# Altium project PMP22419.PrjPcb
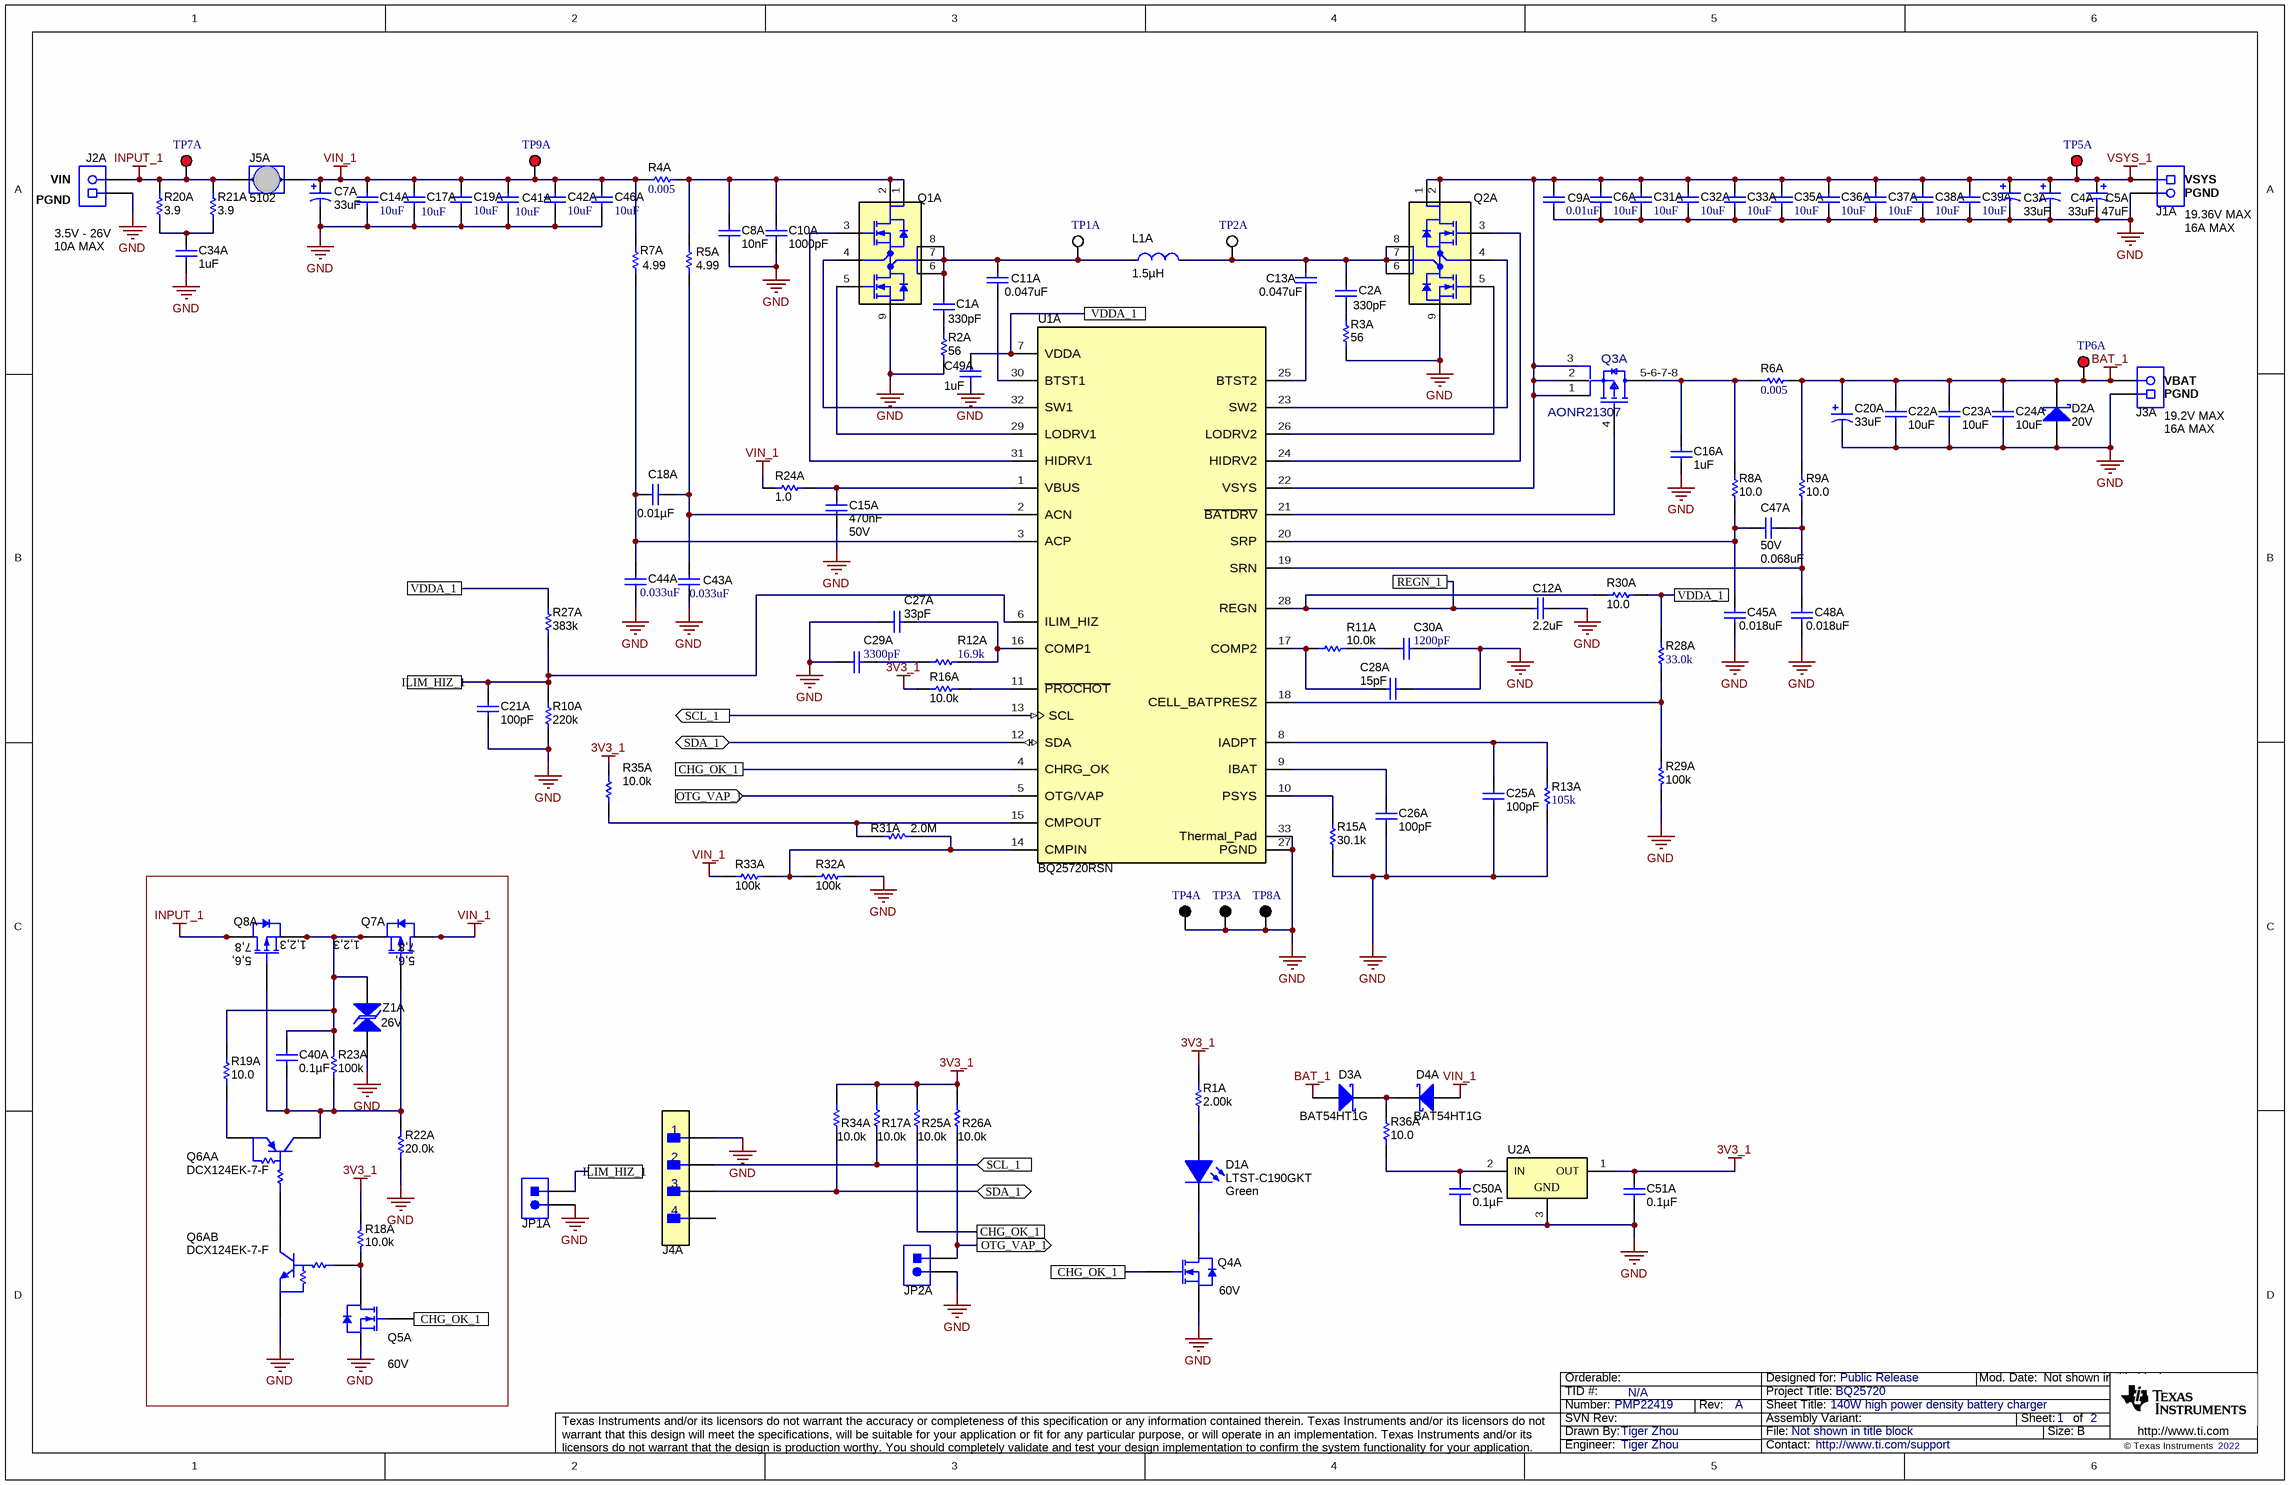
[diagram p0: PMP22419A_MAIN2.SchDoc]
CopyrightYear: 2022; PCB_Layout: Tiger Zhou; PCB_Rev: A; PRJ_Customer: Public Release; PRJ_Engineer: Tiger Zhou; PRJ_Number: PMP22419; PRJ_Title: BQ25720; SCH_Rev: A; TechSupport: http://www.ti.com/support; TID: N/A
1 sheet, 118 parts. Net scope: flat (ports and power ports of the same name join across sheets).
Board file: PMP22419.PcbDoc

## Sheet PMP22419A_MAIN2.SchDoc: 140W high power density battery charger
size 431 x 279 mm; Date: Not shown in title block; ApprovedBy: Not shown in title block; CheckedBy: Not shown in title block; Author: Not shown in title block; CompanyName: Not shown in title block; DrawnBy: Tiger Zhou; Engineer: Not shown in title block; Organization: Not shown in title block; Address1: Not shown in title block; Address2: Not shown in title block; Address3: Not shown in title block; Address4: Not shown in title block; DocumentNumber: 1; Revision: Use project parameter SCH_Rev; SheetNumber: 1; SheetTotal: 2; PageSetup: Record=PageOptions¦CenterHorizontal=True¦CenterVertical=True¦PrintScale=1.00¦XCorrection=1.00¦YCorrection=1.00¦PrintKind=0¦BorderSize=5000000¦LeftOffset=0¦BottomOffset=0¦Orientation=2¦PaperLength=1000¦PaperWidth=1000¦Scale=100¦PaperSource=15¦PrintQuality=600¦MediaType=1¦DitherType=10¦PaperKind=Letter¦PrintScaleMode=1

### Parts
C1A  ValueDisplayed: 330pF  [0603S]  (hidden comment: Capacitor)
C2A  ValueDisplayed: 330pF  [0603S]  (hidden comment: Capacitor)
C3A  ValueDisplayed: 33uF  [7343-31]  (hidden comment: T521D336M035ATE065)
C4A  ValueDisplayed: 33uF  [7343-31]  (hidden comment: T521D336M035ATE065)
C5A  ValueDisplayed: 47uF  [CAPSMT_62_F61]  (hidden comment: Cap_Polarized)
C6A  ValueDisplayed: 10uF  [0805_HV1]  (hidden comment: Capacitor)
C7A  ValueDisplayed: 33uF  [7343-31]  (hidden comment: T521D336M035ATE065)
C8A  Cap_F: 10nF  [0603S]  (hidden comment: GRM188R71H103KA01D)
C9A  ValueDisplayed: 0.01uF  [0603S]  (hidden comment: GRM188R71H103KA01D)
C10A  ValueDisplayed: 1000pF  [0402S]  (hidden comment: C1005NP01H102J050BA)
C11A  ValueDisplayed: 0.047uF  [0603S]  (hidden comment: Capacitor)
C12A  ValueDisplayed: 2.2uF  [0603S]  (hidden comment: Capacitor)
C13A  ValueDisplayed: 0.047uF  [0603S]  (hidden comment: Capacitor)
C14A  ValueDisplayed: 10uF  [0805_HV1]  (hidden comment: Capacitor)
C15A  Cap_F: 470nF  VDC_V: 50V  [0603S]  (hidden comment: C1608X7R1H474K080AC)
C16A  ValueDisplayed: 1uF  [0603S]  (hidden comment: Capacitor)
C17A  ValueDisplayed: 10uF  [0805_HV1]  (hidden comment: Capacitor)
C18A  ValueDisplayed: 0.01µF  [0402S]  (hidden comment: 0402B103K500CT)
C19A  ValueDisplayed: 10uF  [0805_HV1]  (hidden comment: Capacitor)
C20A  ValueDisplayed: 33uF  [7343-31]  (hidden comment: T521D336M035ATE065)
C21A  ValueDisplayed: 100pF  [0402S]  (hidden comment: 04025A101FAT2A)
C22A  ValueDisplayed: 10uF  [1206_180]  (hidden comment: Capacitor)
C23A  ValueDisplayed: 10uF  [1206_180]  (hidden comment: Capacitor)
C24A  ValueDisplayed: 10uF  [1206_180]  (hidden comment: Capacitor)
C25A  ValueDisplayed: 100pF  [0402S]  (hidden comment: 04025A101FAT2A)
C26A  ValueDisplayed: 100pF  [0402S]  (hidden comment: 04025A101FAT2A)
C27A  ValueDisplayed: 33pF  [0402S]  (hidden comment: Capacitor)
C28A  ValueDisplayed: 15pF  [0402S]  (hidden comment: Capacitor)
C29A  ValueDisplayed: 3300pF  [0402S]  (hidden comment: GRM155R71H332KA01D)
C30A  ValueDisplayed: 1200pF  [0402S]  (hidden comment: C0402C122J5GACTU)
C31A  ValueDisplayed: 10uF  [0805_HV1]  (hidden comment: Capacitor)
C32A  ValueDisplayed: 10uF  [0805_HV1]  (hidden comment: Capacitor)
C33A  ValueDisplayed: 10uF  [0805_HV1]  (hidden comment: Capacitor)
C34A  ValueDisplayed: 1uF  [0603S]  (hidden comment: Capacitor)
C35A  ValueDisplayed: 10uF  [0805_HV1]  (hidden comment: Capacitor)
C36A  ValueDisplayed: 10uF  [0805_HV1]  (hidden comment: Capacitor)
C37A  ValueDisplayed: 10uF  [0805_HV1]  (hidden comment: Capacitor)
C38A  ValueDisplayed: 10uF  [0805_HV1]  (hidden comment: Capacitor)
C39A  ValueDisplayed: 10uF  [0805_HV1]  (hidden comment: Capacitor)
C40A  ValueDisplayed: 0.1µF  [0402S]  (hidden comment: 0402BB104KW500)
C41A  ValueDisplayed: 10uF  [0805_HV1]  (hidden comment: Capacitor)
C42A  ValueDisplayed: 10uF  [0805_HV1]  (hidden comment: Capacitor)
C43A  ValueDisplayed: 0.033uF  [0402S]  (hidden comment: CGA2B3X7R1H333K050BB)
C44A  ValueDisplayed: 0.033uF  [0402S]  (hidden comment: CGA2B3X7R1H333K050BB)
C45A  ValueDisplayed: 0.018uF  [0402S]  (hidden comment: GRM155R71H183KA12D)
C46A  ValueDisplayed: 10uF  [0805_HV1]  (hidden comment: Capacitor)
C47A  VDC_V: 50V  ValueDisplayed: 0.068uF  [0402S]  (hidden comment: CGA2B3X7R1H683K050BB)
C48A  ValueDisplayed: 0.018uF  [0402S]  (hidden comment: GRM155R71H183KA12D)
C49A  ValueDisplayed: 1uF  [0603S]  (hidden comment: Capacitor)
C50A  ValueDisplayed: 0.1µF  [0402S]  (hidden comment: 0402BB104KW500)
C51A  ValueDisplayed: 0.1µF  [0402S]  (hidden comment: 0402BB104KW500)
D1A  LTST-C190GKT  value Green  [LED_LTST-C190]
D2A  20V  [SMA]
D3A  BAT54HT1G  [SOD-323]
D4A  BAT54HT1G  [SOD-323]
J1A  Receptacle_2x1  [On-Shore_ED120_2DS]  (value not drawn)
J2A  Receptacle_2x1  [On-Shore_ED120_2DS]  (value not drawn)
J3A  Receptacle_2x1  [On-Shore_ED120_2DS]  (value not drawn)
J4A  22-05-3041  [FP-22-05-3041_HDR4-MFG]  (value not drawn)
J5A  5102  [Keystone_5102]
JP1A  Header_2x1  [CONN_5-146261-1]  (value not drawn)
JP2A  Header_2x1  [CONN_5-146261-1]  (value not drawn)
L1A  Ind_H: 1.5µH  [FP-BMRHDY1010302R2MA1_SMT_IND_11MM2_10MM1-MFG]  (hidden comment: Inductor_Iron)
Q1A  CSD87355Q5D  [DQY0008A]  (value not drawn)
Q2A  CSD87355Q5D  [DQY0008A]  (value not drawn)
Q3A  AONR21307  [FP-AONR21307_DFN8-MFG]
Q4A  value 60V  [SOT-23L]  (hidden comment: MOSFET_N_D3G1S2)
Q5A  value 60V  [SOT-23L]  (hidden comment: MOSFET_N_D3G1S2)
Q6A  DCX124EK-7-F  [SC-74R]  (parts A,B of 2)
Q7A  DMP3035SFG-7  [PowerDI3333-8]  (value not drawn)
Q8A  DMP3035SFG-7  [PowerDI3333-8]  (value not drawn)
R1A  value 2.00k  [0603S]  (hidden comment: Resistor)
R2A  ValueDisplayed: 56  [0603S]  (hidden comment: Resistor)
R3A  ValueDisplayed: 56  [0603S]  (hidden comment: Resistor)
R4A  value 0.005  [1206L]  (hidden comment: WSLP12065L000FEA)
R5A  ValueDisplayed: 4.99  [0402S]  (hidden comment: CRCW04024R99FKED)
R6A  value 0.005  [2010]  (hidden comment: CSNL2010FT5L00)
R7A  ValueDisplayed: 4.99  [0402S]  (hidden comment: CRCW04024R99FKED)
R8A  ValueDisplayed: 10.0  [0402S]  (hidden comment: CRCW040210R0FKED)
R9A  ValueDisplayed: 10.0  [0402S]  (hidden comment: CRCW040210R0FKED)
R10A  ValueDisplayed: 220k  [0402S]  (hidden comment: RC0402FR-07220KL)
R11A  ValueDisplayed: 10.0k  [0402S]  (hidden comment: Resistor)
R12A  ValueDisplayed: 16.9k  [0402S]  (hidden comment: CRCW040216K9FKED)
R13A  ValueDisplayed: 105k  [0402S]  (hidden comment: CRCW0402105KFKED)
R15A  value 30.1k  [0402S]  (hidden comment: CRCW040230K1FKED)
R16A  ValueDisplayed: 10.0k  [0402S]  (hidden comment: CRCW040210K0FKED)
R17A  value 10.0k  [0402S]  (hidden comment: CRCW040210K0FKED)
R18A  ValueDisplayed: 10.0k  [0402S]  (hidden comment: CRCW040210K0FKED)
R19A  ValueDisplayed: 10.0  [1206]  (hidden comment: ERJ-8ENF10R0V)
R20A  value 3.9  [1206]  (hidden comment: Resistor)
R21A  value 3.9  [1206]  (hidden comment: Resistor)
R22A  ValueDisplayed: 20.0k  [0603S]  (hidden comment: CRCW060320K0FKEA)
R23A  ValueDisplayed: 100k  [0402S]  (hidden comment: CRCW0402100KFKED)
R24A  ValueDisplayed: 1.0  [0603S]  (hidden comment: CRCW06031R00JNEA)
R25A  value 10.0k  [0402S]  (hidden comment: CRCW040210K0FKED)
R26A  value 10.0k  [0402S]  (hidden comment: CRCW040210K0FKED)
R27A  ValueDisplayed: 383k  [0402S]  (hidden comment: CRCW0402383KFKED)
R28A  ValueDisplayed: 33.0k  [0402S]  (hidden comment: RC0402FR-0733KL)
R29A  ValueDisplayed: 100k  [0402S]  (hidden comment: CRCW0402100KFKED)
R30A  ValueDisplayed: 10.0  [0402S]  (hidden comment: CRCW040210R0FKED)
R31A  ValueDisplayed: 2.0M  [0402S]  (hidden comment: CRCW04022M00JNED)
R32A  ValueDisplayed: 100k  [0402S]  (hidden comment: CRCW0402100KFKED)
R33A  ValueDisplayed: 100k  [0402S]  (hidden comment: CRCW0402100KFKED)
R34A  value 10.0k  [0402S]  (hidden comment: CRCW040210K0FKED)
R35A  value 10.0k  [0402S]  (hidden comment: CRCW040210K0FKED)
R36A  ValueDisplayed: 10.0  [1206]  (hidden comment: ERJ-8ENF10R0V)
TP1A  5012  [Keystone5012]  (value not drawn)
TP2A  5012  [Keystone5012]  (value not drawn)
TP3A  5011  [Keystone5011]  (value not drawn)
TP4A  5011  [Keystone5011]  (value not drawn)
TP5A  5010  [Keystone5010]  (value not drawn)
TP6A  5010  [Keystone5010]  (value not drawn)
TP7A  5010  [Keystone5010]  (value not drawn)
TP8A  5011  [Keystone5011]  (value not drawn)
TP9A  5010  [Keystone5010]  (value not drawn)
U1A  BQ25720RSN  [RSN0032B-MFG]
U2A  PM-REG-LM3480-SOT3  [DBZ0003A_N]  (value not drawn)
Z1A  value 26V  [SMA_Bi]  (hidden comment: SMAJ26CA)

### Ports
CHG_OK_1, ILIM_HIZ_1, OTG_VAP_1 (in), OTG_VAP_1 (out), REGN_1, SCL_1 (in), SCL_1 (out), SDA_1 (bidir), VDDA_1

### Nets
3V3_1: C51A.2 R1A.2 R16A.1 R17A.2 R18A.2 R25A.2 R26A.1 R34A.2 R35A.1 U2A.1(OUT)
BAT_1: C20A.1(+) C22A.1 C23A.1 C24A.1 D2A.1(K) D3A.2(A) J3A.2 R6A.2 R9A.2 TP6A.1
GND: C3A.2(-) C4A.2(-) C5A.2(-) C6A.2 C7A.2(-) C8A.2 C9A.2 C10A.2 C12A.2 C14A.2 C15A.2 C16A.2 C17A.2 C19A.2 C20A.2(-) C21A.2 C22A.2 C23A.2 C24A.2 C25A.2 C26A.2 C27A.1 C28A.2 C29A.1 C30A.2 C31A.2 C32A.2 C33A.2 C34A.2 C35A.2 C36A.2 C37A.2 C38A.2 C39A.2 C41A.2 C42A.2 C43A.2 C44A.2 C45A.2 C46A.2 C48A.2 C49A.2 C50A.1 C51A.1 D2A.2(A) J1A.2 J2A.1 J3A.1 J4A.1 JP1A.2 JP2A.2 Q1A.9(PGND) Q2A.9(PGND) Q4A.2(S) Q5A.2(S) Q6A.6(E2) R2A.1 R3A.1 R10A.2 R13A.1 R15A.2 R22A.1 R29A.1 R32A.1 TP3A.1 TP4A.1 TP8A.1 U1A.27(PGND) U1A.33(Thermal_Pad) U2A.3(GND) Z1A.2
INPUT_1: J2A.2 J5A.1 Q8A.5(D) Q8A.6(D) Q8A.7(D) Q8A.8(D) Q8A.9(D) R20A.2 R21A.2 TP7A.1
VIN_1: C7A.1(+) C14A.1 C17A.1 C19A.1 C41A.1 C42A.1 C46A.1 D4A.2(A) J5A.2 Q7A.5(D) Q7A.6(D) Q7A.7(D) Q7A.8(D) Q7A.9(D) R4A.1 R7A.2 R24A.1 R33A.2 TP9A.1
VSYS_1: C3A.1(+) C4A.1(+) C5A.1(+) C6A.1 C9A.1 C31A.1 C32A.1 C33A.1 C35A.1 C36A.1 C37A.1 C38A.1 C39A.1 J1A.1 Q2A.1(VIN) Q2A.2(VIN) Q3A.1(S) Q3A.2(S) Q3A.3(S) TP5A.1 U1A.22(VSYS)
CHG_OK_1: Q4A.1(G) Q5A.1(G) R25A.1 U1A.4(CHRG_OK) ; port CHG_OK_1
ILIM_HIZ_1: C21A.1 JP1A.1 R10A.1 R27A.1 U1A.6(ILIM_HIZ) ; port ILIM_HIZ_1
OTG_VAP_1: JP2A.1 R26A.2 U1A.5(OTG/VAP) ; port OTG_VAP_1
REGN_1: C12A.1 R30A.1 U1A.28(REGN) ; port REGN_1
SCL_1: J4A.2 R17A.1 U1A.13(SCL) ; port SCL_1
SDA_1: J4A.3 R34A.1 U1A.12(SDA) ; port SDA_1
VDDA_1: C49A.1 R27A.2 R28A.2 R30A.2 U1A.7(VDDA) ; port VDDA_1
NetC1A_1: C1A.1 C11A.2 L1A.1 Q1A.6(VSW) Q1A.7(VSW) Q1A.8(VSW) TP1A.1
NetC1A_2: C1A.2 R2A.2
NetC2A_1: C2A.1 C13A.2 L1A.2 Q2A.6(VSW) Q2A.7(VSW) Q2A.8(VSW) TP2A.1
NetC2A_2: C2A.2 R3A.2
NetC8A_1: C8A.1 C10A.1 Q1A.1(VIN) Q1A.2(VIN) R4A.2 R5A.2
NetC11A_1: C11A.1 U1A.30(BTST1)
NetC13A_1: C13A.1 U1A.25(BTST2)
NetC15A_1: C15A.1 R24A.2 U1A.1(VBUS)
NetC16A_1: C16A.1 Q3A.5-6-7-8(D) R6A.1 R8A.2
NetC18A_1: C18A.1 C44A.1 R7A.1 U1A.3(ACP)
NetC18A_2: C18A.2 C43A.1 R5A.1 U1A.2(ACN)
NetC25A_1: C25A.1 R13A.2 U1A.8(IADPT)
NetC26A_1: C26A.1 U1A.9(IBAT)
NetC27A_2: C27A.2 R12A.2 U1A.16(COMP1)
NetC28A_1: C28A.1 R11A.1 U1A.17(COMP2)
NetC29A_2: C29A.2 R12A.1
NetC30A_1: C30A.1 R11A.2
NetC34A_1: C34A.1 R20A.1 R21A.1
NetC40A_1: C40A.1 Q6A.4(C1) Q7A.4(G) Q8A.4(G) R22A.2 R23A.1
NetC40A_2: C40A.2 Q7A.1(S) Q7A.2(S) Q7A.3(S) Q8A.1(S) Q8A.2(S) Q8A.3(S) R19A.2 R23A.2 Z1A.1
NetC45A_1: C45A.1 C47A.2 R8A.1 U1A.20(SRP)
NetC47A_1: C47A.1 C48A.1 R9A.1 U1A.19(SRN)
NetC50A_2: C50A.2 R36A.1 U2A.2(IN)
NetD1A_1: D1A.1(A) R1A.1
NetD1A_2: D1A.2(K) Q4A.3(D)
NetD3A_1: D3A.1(K) D4A.1(K) R36A.2
NetQ1A_3: Q1A.3(TG) U1A.31(HIDRV1)
NetQ1A_4: Q1A.4(TGR) U1A.32(SW1)
NetQ1A_5: Q1A.5(BG) U1A.29(LODRV1)
NetQ2A_3: Q2A.3(TG) U1A.24(HIDRV2)
NetQ2A_4: Q2A.4(TGR) U1A.23(SW2)
NetQ2A_5: Q2A.5(BG) U1A.26(LODRV2)
NetQ3A_4: Q3A.4(G) U1A.21(~{BATDRV})
NetQ5A_3: Q5A.3(D) Q6A.5(B2) R18A.1
NetQ6A_1: Q6A.1(C2) Q6A.2(B1)
NetQ6A_3: Q6A.3(E1) R19A.1
NetR15A_1: R15A.1 U1A.10(PSYS)
NetR16A_2: R16A.2 U1A.11(~{PROCHOT})
NetR28A_1: R28A.1 R29A.2 U1A.18(CELL_BATPRESZ)
NetR31A_1: R31A.1 R32A.2 R33A.1 U1A.14(CMPIN)
NetR31A_2: R31A.2 R35A.2 U1A.15(CMPOUT)

Not connected (* = marked no-connect by the designer): J4A 4

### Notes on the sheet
- (near J2A) VIN
- (near J2A) PGND
- 3.5V - 26V
- (near J1A) VSYS
- (near J1A) PGND
- (near J1A) 19.36V MAX
- (near J1A) 16A MAX
- 10A MAX
- (near J3A) PGND
- (near J3A) VBAT
- (near J3A) 19.2V MAX
- (near J3A) 16A MAX

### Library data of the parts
C1A C2A = CMP-0007449-4: CAP, CERM, 330 pF, 50 V, +/- 10%, X7R, 0603; PartNumber: GRM188R71H331KA01D; Manufacturer: MuRata; Polarized: N; Value: 330pF; U/M: EA; Value1: Unknown; VDC_V: 50V; TaMin_C: -55°C; TaMax_C: 125°C; Cap_Case: 0603; SizeAreaWB_mm2: 4.68; SizeZ_mm: 1; SizeX_mm: 1.6; SizeY_mm: 0.8; SizeArea_mm2: 1.28; AEC Category: Q200
C3A C4A C7A C20A = CMP-0011849-2: CAP, TA, 33 uF, 35 V, +/- 20%, 0.065 ohm, SMD; Manufacturer: Kemet; Polarized: Y; CompType: Capacitor; Value: 33uF; U/M: EA; Cap_F: 33µF; VDC_V: 35V; ESR_ohm: 0.065; IRMS_A: 1.9A; TaMin_C: -55°C; TaMax_C: 125°C; AEC Category: Q200; AEC Qualified: N; SizeAreaWB_mm2: 58.59; SizeArea_mm2: 31.39; SizeX_mm: 7.3; SizeY_mm: 4.3; SizeZ_mm: 3.1
C5A = CMP-0012121-3: CAP, Aluminum Polymer, 47 uF, 25 V, +/- 20%, 0.03 ohm, F61 SMD; PartNumber: 25SVPF47M; Manufacturer: Panasonic; Polarized: Y; CompType: Capacitor; Value: 47uF; U/M: EA; Cap_F: 47µF; VDC_V: 25V; ESR_ohm: 0.03; IRMS_A: 2.8A; TaMin_C: -55°C; TaMax_C: 105°C; AEC Category: Q200; SizeAreaWB_mm2: 73.96; SizeZ_mm: 5.8; SizeX_mm: 6.6; SizeArea_mm2: 43.56
C6A C14A C17A C19A C31A C32A C33A C35A C36A C37A C38A C39A C41A C42A C46A = CMP-0007842-2: CAP, CERM, 10 uF, 35 V, +/- 10%, X5R, 0805; PartNumber: C2012X5R1V106K085AC; Manufacturer: TDK; Polarized: N; Value: 10uF; U/M: EA; Cap_F: 10µF; ESR_ohm: 2.818m; Value1: 0.002818 ohm; VDC_V: 35V; IRMS_A: 3.8868A; TaMin_C: -55°C; TaMax_C: 85°C; Cap_Case: 0805; SizeArea_mm2: 2.5; SizeAreaWB_mm2: 6.75; SizeX_mm: 2; SizeY_mm: 1.25; SizeZ_mm: 1.45; AEC Category: Q200
C8A = CMP-0007433-4: CAP, CERM, 0.01 uF, 50 V, +/- 10%, X7R, 0603; Manufacturer: MuRata; Polarized: N; Value: 0.01uF; U/M: EA; Value1: Unknown; VDC_V: 50V; TaMin_C: -55°C; TaMax_C: 125°C; Cap_Case: 0603; AEC Category: Q200; SizeAreaWB_mm2: 4.68; SizeZ_mm: 1; SizeX_mm: 1.6; SizeY_mm: 0.8; SizeArea_mm2: 1.28
C9A = CMP-0007433-4: CAP, CERM, 0.01 uF, 50 V, +/- 10%, X7R, 0603; Manufacturer: MuRata; Polarized: N; Value: 0.01uF; U/M: EA; Cap_F: 10nF; Value1: Unknown; VDC_V: 50V; TaMin_C: -55°C; TaMax_C: 125°C; Cap_Case: 0603; SizeAreaWB_mm2: 4.68; SizeZ_mm: 1; SizeX_mm: 1.6; SizeY_mm: 0.8; SizeArea_mm2: 1.28; AEC Category: Q200
C10A = CMP-0006254-2: CAP, CERM, 1000 pF, 50 V, +/- 5%, C0G/NP0, 0402; Manufacturer: TDK; Polarized: N; Value: 1000pF; U/M: EA; Cap_F: 1nF; Value1: Unknown; VDC_V: 50V; TaMin_C: -55°C; TaMax_C: 150°C; Cap_Case: 0402; SizeAreaWB_mm2: 3; SizeZ_mm: 0.6; SizeX_mm: 1; SizeY_mm: 0.5; AEC Category: Q200
C11A C13A = CMP-0007423-4: CAP, CERM, 0.047 uF, 25 V, +/- 10%, X7R, 0603; PartNumber: GRM188R71E473KA01D; Manufacturer: MuRata; Polarized: N; U/M: EA; Cap_F: 47nF; Value1: Unknown; VDC_V: 25V; TaMin_C: -55°C; TaMax_C: 125°C; Cap_Case: 0603; SizeAreaWB_mm2: 4.68; SizeZ_mm: 1; SizeX_mm: 1.6; SizeY_mm: 0.8; SizeArea_mm2: 1.28; AEC Category: Q200
C12A = CMP-0007356-5: CAP, CERM, 2.2 uF, 35 V, +/- 10%, X5R, 0603; PartNumber: GRM188R6YA225KA12D; Manufacturer: MuRata; Polarized: N; Value: 2.2uF; U/M: EA; Cap_F: 2.2µF; Value1: Unknown; VDC_V: 35V; TaMin_C: -55°C; TaMax_C: 85°C; Cap_Case: 0603; SizeAreaWB_mm2: 4.68; SizeZ_mm: 1; SizeX_mm: 1.6; SizeY_mm: 0.8; SizeArea_mm2: 1.28; AEC Category: Q200
C15A = CMP-0007050-4: CAP, CERM, 0.47 uF, 50 V, +/- 10%, X7R, 0603; Manufacturer: TDK; Polarized: N; Value: 0.47uF; U/M: EA; ESR_ohm: 10.974m; Value1: 0.010974 ohm; IRMS_A: 1.5748A; TaMin_C: -55°C; TaMax_C: 125°C; Cap_Case: 0603; AEC Category: Q200; SizeAreaWB_mm2: 4.68; SizeZ_mm: 1; SizeX_mm: 1.6; SizeY_mm: 0.8; SizeArea_mm2: 1.28
C16A C34A C49A = CMP-0007405-4: CAP, CERM, 1 uF, 25 V, +/- 10%, X7R, 0603; PartNumber: GRM188R71E105KA12D; Manufacturer: MuRata; Polarized: N; Value: 1uF; U/M: EA; Cap_F: 1µF; Value1: Unknown; VDC_V: 25V; TaMin_C: -55°C; TaMax_C: 125°C; Cap_Case: 0603; SizeAreaWB_mm2: 4.68; SizeZ_mm: 1; SizeX_mm: 1.6; SizeY_mm: 0.8; SizeArea_mm2: 1.28; AEC Category: Q200
C18A = CMP-0085842-1: CAP, CERM, 0.01 µF, 50 V,+/- 10%, X7R, 0402; Manufacturer: Walsin; Polarized: N; Value: 0.01uF; U/M: EA; Cap_F: 10nF; VDC_V: 50V; TaMin_C: -55°C; TaMax_C: 125°C; Cap_Case: 0402; AEC Category: Q200; SizeAreaWB_mm2: 3; SizeZ_mm: 0.6; SizeX_mm: 1; SizeY_mm: 0.5
C21A C25A C26A = CMP-0006196-2: CAP, CERM, 100 pF, 50 V, +/- 1%, C0G/NP0, 0402; Manufacturer: AVX; Value: 100pF; VDC_V: 50V; SizeZ_mm: 0.6; AEC Qualified: N; TaMin_C: -55°C; SizeAreaWB_mm2: 3; Value1: Unknown; U/M: EA; TaMax_C: 125°C; SizeX_mm: 1; SizeY_mm: 0.5; Cap_Case: 0402; AEC Category: Q200
C22A C23A C24A = CMP-0008965-2: CAP, CERM, 10 uF, 25 V, +/- 10%, X7R, 1206; PartNumber: GRM31CR71E106KA12L; Manufacturer: MuRata; Polarized: N; Value: 10uF; U/M: EA; Cap_F: 10µF; Value1: Unknown; VDC_V: 25V; TaMin_C: -55°C; TaMax_C: 125°C; Cap_Case: 2220; SizeArea_mm2: 5.12; SizeAreaWB_mm2: 10.92; SizeX_mm: 3.2; SizeY_mm: 1.6; SizeZ_mm: 1.8; AEC Category: Q200
C27A = CMP-0006454-2: CAP, CERM, 33 pF, 50 V, +/- 5%, C0G/NP0, 0402; PartNumber: GRM1555C1H330JA01D; Manufacturer: MuRata; Polarized: N; Value: 33pF; U/M: EA; Value1: Unknown; VDC_V: 50V; TaMin_C: -55°C; TaMax_C: 125°C; Cap_Case: 0402; AEC Category: Q200; SizeArea_mm2: 0.5; SizeAreaWB_mm2: 3; SizeX_mm: 1; SizeZ_mm: 0.6
C28A = CMP-0006420-2: CAP, CERM, 15 pF, 50 V, +/- 5%, C0G/NP0, 0402; PartNumber: GRM1555C1H150JA01D; Manufacturer: MuRata; Polarized: N; Value: 15pF; U/M: EA; Value1: Unknown; VDC_V: 50V; TaMin_C: -55°C; TaMax_C: 125°C; Cap_Case: 0402; AEC Category: Q200; SizeAreaWB_mm2: 3; SizeZ_mm: 0.6; SizeX_mm: 1; SizeY_mm: 0.5
C29A = CMP-0006688-2: CAP, CERM, 3300 pF, 50 V, +/- 10%, X7R, 0402; Manufacturer: MuRata; Polarized: N; Value: 3300pF; U/M: EA; Cap_F: 3.3nF; Value1: Unknown; VDC_V: 50V; TaMin_C: -55°C; TaMax_C: 125°C; Cap_Case: 0402; AEC Category: Q200; SizeAreaWB_mm2: 3; SizeZ_mm: 0.6; SizeX_mm: 1; SizeY_mm: 0.5
C30A = CMP-0006240-2: CAP, CERM, 1200 pF, 50 V, +/- 5%, C0G/NP0, 0402; Manufacturer: Kemet; Polarized: N; Value: 1200pF; U/M: EA; Cap_F: 1.2nF; Value1: Unknown; VDC_V: 50V; TaMin_C: -55°C; TaMax_C: 125°C; Cap_Case: 0402; AEC Category: Q200; SizeAreaWB_mm2: 3; SizeZ_mm: 0.6; SizeX_mm: 1; SizeY_mm: 0.5
C40A C50A C51A = CMP-0860983-1: CAP, CERM, 0.1 µF, 50 V,+/- 10%, X7R, 0402; Manufacturer: Passive Plus; Polarized: N; Value: 0.1uF; U/M: EA; Cap_F: 100nF; VDC_V: 50V; TaMin_C: -55°C; TaMax_C: 125°C; Cap_Case: 0402; SizeAreaWB_mm2: 3; SizeZ_mm: 0.6; SizeX_mm: 1; SizeY_mm: 0.5; AEC Category: Q200
C43A C44A = CMP-0006329-2: CAP, CERM, 0.033 uF, 50 V, +/- 10%, X7R, AEC-Q200 Grade 1, 0402; Manufacturer: TDK; Polarized: N; U/M: EA; Cap_F: 33nF; ESR_ohm: 98.477m; Value1: 0.098477 ohm; VDC_V: 50V; IRMS_A: 530.78mA; TaMin_C: -55°C; TaMax_C: 125°C; Cap_Case: 0402; AEC Category: Q200; AEC Qualified: Y; AEC Grade: 1; SizeArea_mm2: 0.5; SizeAreaWB_mm2: 3; SizeZ_mm: 0.6
C45A C48A = CMP-0006681-2: CAP, CERM, 0.018 uF, 50 V, +/- 10%, X7R, 0402; Manufacturer: MuRata; Polarized: N; U/M: EA; Cap_F: 18nF; Value1: Unknown; VDC_V: 50V; TaMin_C: -55°C; TaMax_C: 125°C; Cap_Case: 0402; AEC Category: Q200; SizeArea_mm2: 0.5; SizeAreaWB_mm2: 3; SizeX_mm: 1; SizeZ_mm: 0.6
C47A = CMP-0006331-2: CAP, CERM, 0.068 uF, 50 V, +/- 10%, X7R, AEC-Q200 Grade 1, 0402; Manufacturer: TDK; TaMin_C: -55°C; ESR_ohm: 0.05606; Polarized: N; SizeAreaWB_mm2: 3; Value1: 0.05606 ohm; U/M: EA; TaMax_C: 125°C; SizeZ_mm: 0.6; SizeX_mm: 1; SizeY_mm: 0.5; Cap_Case: 0402; AEC Qualified: Y; Cap_F: 68nF; IRMS_A: 684.724mA; AEC Category: Q200
D1A = CMP-0002827-3: LED, Green, SMD; Manufacturer: Lite-On; Vf_V: 2.1V; Io_A: 20mA; Power_TotalModule: 100mW; Value1: 0.1W
D2A = CMP-0028399-2: Diode, Schottky, 20 V, 2 A, SMA; PartNumber: B220A-13-F; Manufacturer: Diodes Inc.; Vf_V: 500mV; Value1: 2A; Value2: 0.5V; TJmax_C: 150°C; RJC_CperW: 20; AEC Category: Q101; Green_Lifecycle: Active; Green_REACh: Passed; SizeArea_mm2: 16.3228; SizeAreaWB_mm2: 37.3428; SizeX_mm: 5.59; SizeY_mm: 2.92; SizeZ_mm: 2.87
D3A D4A = CMP-0028455-2: Diode, Schottky, 30 V, 0.2 A, SOD-323; Manufacturer: ON Semiconductor; Value: 30V; Vf_V: 350mV; Value1: 0.2A; Value2: 0.35V; Io_A: 200mA; Green_Lifecycle: Active; SizeAreaWB_mm2: 8.695; Green_REACh: Passed; SizeZ_mm: 1; SizeX_mm: 2.7; SizeY_mm: 1.35; SizeArea_mm2: 3.645; AEC Category: Q101
J1A J2A J3A = CMP-0074910-1: Terminal Block, 5.08 mm, 2x1, Brass, TH; PartNumber: ED120/2DS; Manufacturer: On-Shore Technology; U/M: EA; Cert_VDE: Y; CNHeader: False; Current_A: 15A; Green_Lifecycle: Not Set; Shrouded: N; Gender: Female; Green_REACh: Incomplete; Voltage_V: 300V; Row_Count: 1; Pitch_mm: 5.08; CT: True
J4A = CMP-0089047-2: Connector Header Through Hole, Right Angle 4 position 0.100" (2.54mm); Manufacturer: Molex; PartNumber: 0022053041; Row_Count: 1; Current_A: 4A; ContactFinish: Tin,Nickel; Voltage_V: 500V
J5A = CMP-0055135-1: Shorting Jumper, 5.375mm, 2 Position, Tin, SMT; Manufacturer: Keystone; CNHeader: FALSE; Pitch_mm: 5.375
JP1A JP2A = CMP-0054947-1: Header, 100mil, 2x1, Gold, TH; PartNumber: 5-146261-1; Manufacturer: TE Connectivity; SymbolCreator: a0412235; U/M: EA; CT: FALSE; Green_REACh: Passed; CNHeader: TRUE; Green_Lifecycle: Active
L1A = CMP-0088941-1: 2.2µH Shielded Wirewound Inductor 13A 9mOhm Max 10x10x3mm; PartNumber: BMRHDY1010302R2MA1; Manufacturer: Chilisin Electronics; SizeZ_mm: 3mm; Material: Magnetic Metal Powder; DCR_ohm: 9m; Tolerance_%: 20%; AEC Qualified: No; Test Frequency: 100kHz; Isat: 16A
Q1A Q2A = CMP-0000606-2: MOSFET, 2-CH, N-CH, 30 V, 45 A, DQY0008A (LSON-CLIP-8); Manufacturer: Texas Instruments; Alternate Manufacturer: None; ChType: N; QgTyp_nC: 10.5; SizeAreaWB_mm2: 56; SizeArea_mm2: 30; IdsMax_A: 45A; VdsMax_V: 30V; Rdson45_ohm: 4.7m; Vgs_V: 10V; AEC Category: Q101; Value: 30V; SizeZ_mm: 1.6; ChMode: Enhancement; SizeY_mm: 5; Value2: 10.5 nC; Value1: 0.004; SizeX_mm: 6
Q3A = CMP-0088961-1: MOSFET P-CH 30V 3X3 DFN; Manufacturer: Alpha & Omega Semiconductor; SizeZ_mm: 0.9mm; IdsMax_A: -24A; Vgs_V: 25V; AEC Qualified: No; Rdson45_ohm: 9.2m; ChMode: False; VdsMax_V: -1V; QgTyp_nC: 35nC @ -10V; Threshold Vgs Max: -2.3V; Reverse Recovery Time: 13.3ns; Power_W: 5W; TJmax_C: +150°C; Drain To Source Breakdown Voltage: -30V; Input Capacitace At Vds: 1995pF @ -15V; Reverse Recovery Charge: 20nC; Threshold Vgs Min: -1.3V; Number Of Channels: 1; Pulse Drain Current: -82A; Turn On Delay Time: 11ns; Rthja Max: 45°C/W; Standoff Height: 0mm; Turn Off Delay Time: 43.5ns; Typ Forward Diode Voltage: -0.7V
Q4A = CMP-0000772-1: MOSFET, N-CH, 60 V, 0.26 A, SOT-23; PartNumber: 2N7002ET1G; Manufacturer: ON Semiconductor; Alternate Manufacturer: None; U/M: EA; ChType: N; Rdson45_ohm: 3; Value2: 0.81 nC; QgTyp_nC: 0.81; Vgs_V: 20V; IdsMax_A: 2.6dA; AEC Category: Q101; SizeZ_mm: 1.1; SizeX_mm: 2.5; SizeArea_mm2: 7.5; SizeAreaWB_mm2: 14
Q5A = CMP-0000772-1: MOSFET, N-CH, 60 V, 0.26 A, SOT-23; PartNumber: 2N7002ET1G; Manufacturer: ON Semiconductor; Alternate Manufacturer: None; U/M: EA; ChType: N; Rdson45_ohm: 3; Value2: 0.81 nC; QgTyp_nC: 0.81; Vgs_V: 20V; IdsMax_A: 2.6dA; SizeZ_mm: 1.1; SizeX_mm: 2.5; SizeArea_mm2: 7.5; AEC Category: Q101; SizeAreaWB_mm2: 14
Q6A = CMP-0000514-2: Transistor, NPN/PNP Pair, 50 V, 0.05 A, SC-74R; Manufacturer: Diodes Inc.; CompType: BJT; U/M: EA; Value1: 0.05 A; Value2: 600; Value: 50 V; SymbolCreator: Altium; PNP: 1; Vceo_V: 50V; Vcesat1_V: 3dV; IcRated_A: 50mA; TaMin_C: -55°C; TaMax_C: 150°C; SizeX_mm: 2.8; SizeY_mm: 3; SizeZ_mm: 1.4; SizeArea_mm2: 8.4; AEC Category: Q101; SizeAreaWB_mm2: 15.2
Q7A Q8A = CMP-0000041-3: MOSFET, P-CH, -30 V, -8.5 A, AEC-Q101, 8-PowerVDFN; Manufacturer: Diodes Inc.; Alternate Manufacturer: None; ChType: P; Value: -30V; Value2: 35.5 nC; QgTyp_nC: 35.5; Vgs_V: -25V; IdsMax_A: -8.5A; SizeZ_mm: 0.8; SizeX_mm: 3.3; AEC Qualified: Y; SizeArea_mm2: 10.89; AEC Category: Q101; SizeAreaWB_mm2: 18.49; ChMode: Enhancement
R1A = CMP-0022268-4: RES, 2.00 k, 1%, 0.1 W, AEC-Q200 Grade 0, 0603; PartNumber: CRCW06032K00FKEA; Manufacturer: Vishay-Dale; Res_ohm: 2k; Value_Code: 2k00; Power_W: 100mW; Value2: 0.1W; VDC_V: 75V; TempCo: 100 ppm/C; EIA_Code: E96; U/M: EA; SizeX_mm: 1.6; SizeY_mm: 0.8; SizeZ_mm: 1; SizeArea_mm2: 1.28; AEC Qualified: Y; AEC Category: Q200; AEC Grade: 0
R2A R3A = CMP-0025829-4: RES, 56, 5%, 0.1 W, AEC-Q200 Grade 0, 0603; PartNumber: CRCW060356R0JNEA; Manufacturer: Vishay-Dale; Value: 56; Value_Code: 56R0; Power_W: 100mW; Value2: 0.1W; VDC_V: 75V; TempCo: 200 ppm/C; EIA_Code: E24; U/M: EA; SizeX_mm: 1.6; SizeY_mm: 0.8; SizeZ_mm: 1; SizeArea_mm2: 1.28; AEC Qualified: Y; AEC Category: Q200; AEC Grade: 0
R4A = CMP-0084411-1: RES, 0.005, 1%, 1 W, AEC-Q200 Grade 0, 1206; Manufacturer: Vishay-Dale; Res_ohm: 5m; Value_Code: 5L000; Power_W: 1W; TempCo: 110 ppm/C; EIA_Code: E96; SizeX_mm: 3.2; SizeY_mm: 1.6; SizeZ_mm: 1.35; SizeArea_mm2: 5.12; AEC Qualified: Y; AEC Category: Q200; AEC Grade: 0; Green_REACh: Passed; Green_Lifecycle: Active; SizeAreaWB_mm2: 10.92
R5A R7A = CMP-0026434-2: RES, 4.99, 1%, 0.063 W, AEC-Q200 Grade 0, 0402; Manufacturer: Vishay-Dale; Value: 4.99; Value_Code: 4R99; Power_W: 63mW; Value2: 0.063W; VDC_V: 50V; TempCo: 100 ppm/C; EIA_Code: E96; AEC Category: Q200; AEC Qualified: Y; AEC Grade: 0; SizeArea_mm2: 0.5; SizeX_mm: 1; SizeZ_mm: 0.6
R6A = CMP-0016512-2: RES, 0.005, 1%, 1.5 W, 2010; Manufacturer: Stackpole Electronics Inc; Res_ohm: 5m; Value_Code: 5L000; Power_W: 1.5W; TempCo: 50 ppm/C; EIA_Code: E96; U/M: EA; SizeX_mm: 5; SizeY_mm: 2.5; SizeZ_mm: 1.66; SizeArea_mm2: 12.5; AEC Category: Q200
R8A R9A R30A = CMP-0025963-3: RES, 10.0, 1%, 0.063 W, AEC-Q200 Grade 0, 0402; Manufacturer: Vishay-Dale; Value: 10.0; Res_ohm: 10; Value_Code: 10R0; Power_W: 63mW; Value2: 0.063W; VDC_V: 50V; TempCo: 100 ppm/C; EIA_Code: E96; SizeX_mm: 1; SizeY_mm: 0.5; SizeZ_mm: 0.6; AEC Qualified: Y; AEC Category: Q200; AEC Grade: 0
R10A = CMP-0026728-1: RES, 220 k, 1%, 0.0625 W, 0402; Manufacturer: Yageo America; Value: 220k; Power_W: 62.5mW; VDC_V: 50V; TempCo: 100 ppm/C; SizeX_mm: 1; SizeY_mm: 0.5; SizeZ_mm: 0.6; AEC Qualified: N; AEC Category: Q200; U/M: EA
R11A = CMP-0025958-3: RES, 10.0 k, 1%, 0.063 W, AEC-Q200 Grade 0, 0402; PartNumber: CRCW040210K0FKED; Manufacturer: Vishay-Dale; Value: 10.0k; Res_ohm: 10k; Value_Code: 10k0; Power_W: 63mW; Value2: 0.063W; VDC_V: 50V; TempCo: 100 ppm/C; EIA_Code: E96; U/M: EA; AEC Category: Q200; AEC Qualified: Y; AEC Grade: 0; SizeArea_mm2: 0.5; SizeX_mm: 1; SizeZ_mm: 0.6
R12A = CMP-0026042-3: RES, 16.9 k, 1%, 0.063 W, AEC-Q200 Grade 0, 0402; Manufacturer: Vishay-Dale; Value: 16.9k; Value_Code: 16k9; Power_W: 63mW; Value2: 0.063W; VDC_V: 50V; TempCo: 100 ppm/C; EIA_Code: E96; AEC Category: Q200; AEC Qualified: Y; AEC Grade: 0; SizeX_mm: 1; SizeY_mm: 0.5; SizeZ_mm: 0.6
R13A = CMP-0025954-3: RES, 105 k, 1%, 0.063 W, AEC-Q200 Grade 0, 0402; Manufacturer: Vishay-Dale; Value: 105k; Power_W: 63mW; Value2: 0.063W; VDC_V: 50V; TempCo: 100 ppm/C; EIA_Code: E96; AEC Category: Q200; AEC Qualified: Y; AEC Grade: 0; SizeArea_mm2: 0.5; SizeX_mm: 1; SizeZ_mm: 0.6
R15A = CMP-0026284-2: RES, 30.1 k, 1%, 0.063 W, AEC-Q200 Grade 0, 0402; Manufacturer: Vishay-Dale; Value_Code: 30k1; Power_W: 63mW; Value2: 0.063W; VDC_V: 50V; TempCo: 100 ppm/C; EIA_Code: E96; SizeX_mm: 1; SizeY_mm: 0.5; SizeZ_mm: 0.6; AEC Qualified: Y; AEC Category: Q200; AEC Grade: 0
R16A R18A = CMP-0025958-3: RES, 10.0 k, 1%, 0.063 W, AEC-Q200 Grade 0, 0402; Manufacturer: Vishay-Dale; Value: 10.0k; Res_ohm: 10k; Value_Code: 10k0; Power_W: 63mW; Value2: 0.063W; VDC_V: 50V; TempCo: 100 ppm/C; EIA_Code: E96; SizeX_mm: 1; SizeY_mm: 0.5; SizeZ_mm: 0.6; AEC Qualified: Y; AEC Category: Q200; AEC Grade: 0
R17A R25A R26A R34A R35A = CMP-0025958-3: RES, 10.0 k, 1%, 0.063 W, AEC-Q200 Grade 0, 0402; Manufacturer: Vishay-Dale; Res_ohm: 10k; Value_Code: 10k0; Power_W: 63mW; Value2: 0.063W; VDC_V: 50V; TempCo: 100 ppm/C; EIA_Code: E96; SizeX_mm: 1; SizeY_mm: 0.5; SizeZ_mm: 0.6; AEC Qualified: Y; AEC Category: Q200; AEC Grade: 0
R19A R36A = CMP-0017299-3: RES, 10.0, 1%, 0.25 W, AEC-Q200 Grade 0, 1206; Manufacturer: Panasonic; Value: 10.0; Res_ohm: 10; Value_Code: 10R0; Power_W: 250mW; Value2: 0.25W; VDC_V: 200V; TempCo: 100 ppm/C; EIA_Code: E96; SizeX_mm: 3.2; SizeY_mm: 1.6; SizeZ_mm: 1.35; SizeArea_mm2: 5.12; AEC Qualified: Y; AEC Category: Q200; AEC Grade: 0; SizeAreaWB_mm2: 10.92
R20A R21A = CMP-0018679-3: RES, 3.9, 5%, 0.25 W, AEC-Q200 Grade 0, 1206; PartNumber: CRCW12063R90JNEA; Manufacturer: Vishay-Dale; Value_Code: 3R90; Power_W: 250mW; Value2: 0.25W; VDC_V: 200V; TempCo: 200 ppm/C; EIA_Code: E24; U/M: EA; SizeX_mm: 3.2; SizeY_mm: 1.6; SizeZ_mm: 1.35; SizeArea_mm2: 5.12; AEC Qualified: Y; AEC Category: Q200; AEC Grade: 0
R22A = CMP-0022204-4: RES, 20.0 k, 1%, 0.1 W, AEC-Q200 Grade 0, 0603; Manufacturer: Vishay-Dale; Value: 20.0k; Res_ohm: 20k; Value_Code: 20k0; Power_W: 100mW; Value2: 0.1W; VDC_V: 75V; TempCo: 100 ppm/C; EIA_Code: E96; SizeX_mm: 1.6; SizeY_mm: 0.8; SizeZ_mm: 1; SizeArea_mm2: 1.28; AEC Qualified: Y; AEC Category: Q200; AEC Grade: 0
R23A R29A = CMP-0025950-3: RES, 100 k, 1%, 0.063 W, AEC-Q200 Grade 0, 0402; Manufacturer: Vishay-Dale; Value: 100k; Power_W: 63mW; Value2: 0.063W; VDC_V: 50V; TempCo: 100 ppm/C; EIA_Code: E96; SizeX_mm: 1; SizeY_mm: 0.5; SizeZ_mm: 0.6; AEC Qualified: Y; AEC Category: Q200; AEC Grade: 0
R24A = CMP-0025743-4: RES, 1.0, 5%, 0.1 W, AEC-Q200 Grade 0, 0603; Manufacturer: Vishay-Dale; Value: 1.0; Res_ohm: 1; Value_Code: 1R00; Power_W: 100mW; Value2: 0.1W; VDC_V: 75V; TempCo: 200 ppm/C; EIA_Code: E24; AEC Category: Q200; AEC Qualified: Y; AEC Grade: 0; SizeX_mm: 1.6; SizeY_mm: 0.8; SizeArea_mm2: 1.28
R27A = CMP-0026321-2: RES, 383 k, 1%, 0.063 W, AEC-Q200 Grade 0, 0402; Manufacturer: Vishay-Dale; Value: 383k; Power_W: 63mW; Value2: 0.063W; VDC_V: 50V; TempCo: 100 ppm/C; EIA_Code: E96; SizeX_mm: 1; SizeY_mm: 0.5; SizeZ_mm: 0.6; AEC Qualified: Y; AEC Category: Q200; AEC Grade: 0
R28A = CMP-0078584-1: RES, 33.0 k, 1%, 0.063 W, 0402; Manufacturer: Yageo America; Power_W: 63mW; TempCo: 100 ppm/C; Value_Code: 33k0; Value: 33.0k; Res_ohm: 33k; SizeX_mm: 1; SizeY_mm: 0.5; SizeZ_mm: 0.6; Value2: 0.063W; AEC Qualified: N; AEC Category: Q200
R31A = CMP-0026893-2: RES, 2.0 M, 5%, 0.063 W, AEC-Q200 Grade 0, 0402; Manufacturer: Vishay-Dale; Value: 2.0Meg; Res_ohm: 2M; Value_Code: 2M00; Power_W: 63mW; Value2: 0.063W; VDC_V: 50V; TempCo: 200 ppm/C; EIA_Code: E24; SizeX_mm: 1; SizeY_mm: 0.5; SizeZ_mm: 0.6; AEC Qualified: Y; AEC Category: Q200; AEC Grade: 0
R32A R33A = CMP-0025950-3: RES, 100 k, 1%, 0.063 W, AEC-Q200 Grade 0, 0402; Manufacturer: Vishay-Dale; Power_W: 63mW; TempCo: 100 ppm/C; Value: 100k; EIA_Code: E96; SizeX_mm: 1; SizeY_mm: 0.5; SizeZ_mm: 0.6; Value2: 0.063W; AEC Qualified: Y; VDC_V: 50V; AEC Category: Q200; AEC Grade: 0
TP1A TP2A = CMP-0055149-1: Test Point, Multipurpose, White, TH; Manufacturer: Keystone; CNHeader: FALSE; Green_Lifecycle: Active; Green_REACh: Passed; CT: TRUE; ContactFinish: Silver
TP3A TP4A TP8A = CMP-0055148-1: Test Point, Multipurpose, Black, TH; Manufacturer: Keystone; CNHeader: FALSE; Green_Lifecycle: Active; Green_REACh: Passed; CT: TRUE; ContactFinish: Silver
TP5A TP6A TP7A TP9A = CMP-0055147-1: Test Point, Multipurpose, Red, TH; Manufacturer: Keystone; CNHeader: FALSE; Green_Lifecycle: Active; Green_REACh: Passed; CT: TRUE; ContactFinish: Silver
U1A = CMP-0089011-2: No description; Manufacturer: Texas Instruments; AEC Category: Q200; SizeZ_mm: 0.8mm; CompType: IC
U2A = CMP-0071020-1: 100 mA, Quasi Low-Dropout Linear Voltage Regulator, 3-pin SOT-23, Pb-Free; PartNumber: LM3480IM3-3.3/NOPB; Manufacturer: Texas Instruments; PackageTopMarking: L0A*XTT; PowerWise: N; CompType: LDO IC
Z1A = CMP-0085013-1: Diode, TVS, Bi, 26 V, 42.1 Vc, 400 W, 9.5 A, SMA (non-polarized); Manufacturer: Littelfuse; Value1: 42.1V; RJA_CperW: 120; SizeAreaWB_mm2: 32.368125; SizeZ_mm: 2.65; SizeX_mm: 5.075; SizeY_mm: 2.575; SizeArea_mm2: 13.068125; AEC Qualified: N; AEC Category: Q101; Ppk: 400W; Vbr_Min: 28.9V; Ipp: 9.5A; Vbr_Max: 31.9V

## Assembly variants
001: not fitted C1 C1A C2 C2A C4 C4A C5 C5A C18 C18A C20 C20A C24 C24A C39 C39A C40 C40A C45 C45A C47 C47A C48 C48A D2 D2A Q5 Q5A Q6 Q6A Q7 Q7A Q8 Q8A R2 R2A R3 R3A R14 R14A R16 R16A R17 R17A R18 R18A R19 R19A R22 R22A R23 R23A R25 R25A R26 R26A R31 R31A R33 R33A R34 R34A R35 R35A Z1 Z1A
